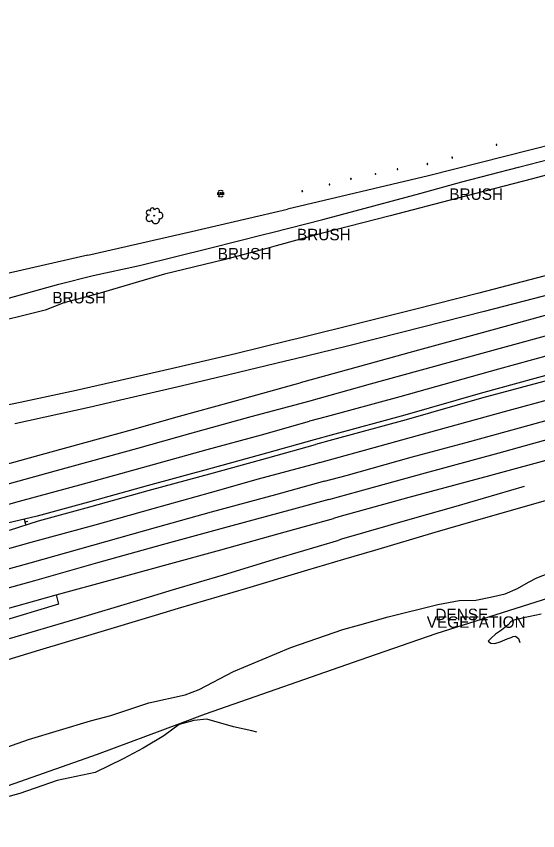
# Model space of a CAD drawing. Extents: x 2129547 to 2134906, y 657330 to 659734.
# Drawn here: x 2134074.5 to 2134392.5, y 658778.9 to 659275.8 of the extents above; entities that cross this region are included whole.
import ezdxf

# ---------------------------------------------------------------- set-up
doc = ezdxf.new("R2010")
doc.units = 0
for name, color, linetype in [('PM_X_Edge_Line', 7, 'Continuous'), ('PM_X_Lane_Line', 7, 'Continuous'), ('PV_X_EOP2', 7, 'Continuous'), ('RD_X_Concrete_Barrier', 7, 'Continuous'), ('RD_X_Fence', 7, 'Continuous'), ('SN_X_Public', 7, 'Continuous'), ('UT_X_Unknown_Cells', 7, 'Continuous'), ('VG_X_Cells', 7, 'Continuous'), ('VG_X_Shrub_Line_Lt', 7, 'Continuous'), ('VG_X_Text', 7, 'Continuous'), ('VG_X_Tree_Line_Lt', 7, 'Continuous')]:
    doc.layers.add(name, color=color, linetype=linetype)

# ---------------------------------------------------------------- blocks, each defined once
blk = doc.blocks.new('SGN1P')
at = {"layer": 'SN_X_Public'}
for p, q in [((0, 0), (-0.02032, 0)), ((0, 0.02032), (0, -0.02032))]:
    blk.add_line(p, q, dxfattribs=at)
blk = doc.blocks.new('TREE')
at = {"layer": 'VG_X_Cells'}
blk.add_circle((0, 0), 0.00305, dxfattribs=at)
for centre, radius, start, end in [((-0.0362, -0.0197), 0.0251, 96.17219, 320.57371), ((-0.042, 0.0237), 0.0187, 39.06254, 279.54124), ((-0.0125, 0.0428), 0.0167, 354.0047, 205.97412), ((0.0232, 0.0359), 0.0197, 323.82996, 165.0376), ((0.0439, 0.0005), 0.0243, 259.14531, 101.45961), ((0.012, -0.0331), 0.029, 184.94757, 19.45715)]:
    blk.add_arc(centre, radius, start, end, dxfattribs=at)
blk = doc.blocks.new('UMH')
at = {"layer": 'UT_X_Unknown_Cells'}
for p, q in [((-0.017, 0.0104), (-0.017, -0.0059)), ((-0.0042, 0.0104), (-0.0042, -0.0059))]:
    blk.add_line(p, q, dxfattribs=at)
blk.add_lwpolyline([(0.0024, -0.01), (0.0024, 0.0104), (0.0099, -0.01), (0.0174, 0.0104), (0.0174, -0.01)], dxfattribs=at)
for centre, radius, start, end in [((0, 0), 0.0254, 160.01689, 200.03919), ((0, 0), 0.0254, 100.0806, 140.07213), ((0, 0), 0.0254, 40.05767, 80.10608), ((0, 0), 0.0254, 340.01689, 20.03919), ((0, 0), 0.0254, 220.05767, 260.04731), ((-0.0106, -0.0029), 0.00708, 205.19243, 334.80757), ((0, 0), 0.0254, 280.01144, 320.02638)]:
    blk.add_arc(centre, radius, start, end, dxfattribs=at)

msp = doc.modelspace()

# ---------------------------------------------------------------- linework, layer by layer
at = {"layer": 'PM_X_Edge_Line'}
for points in [[(2134723.56, 659210.16), (2134667.28, 659193.75), (2134606.38, 659176.46), (2134554.94, 659161.67), (2134501.09, 659146.16), (2134449.29, 659131.67), (2134400.95, 659118.53), (2134356.58, 659106.88), (2134317.3, 659096.98), (2134285.7, 659088.97), (2134246.38, 659079.32), (2134241.17, 659078.04)], [(2134735.23, 659162.91), (2134721.25, 659158.93), (2134671.25, 659144.73), (2134621.41, 659130.82), (2134574.26, 659117.65), (2134524.14, 659103.87), (2134472.09, 659089.42), (2134420.46, 659074.83), (2134368.59, 659060.49), (2134308.4, 659043.65), (2134263.44, 659031.51), (2134253.36, 659028.71)], [(2134259.57, 659003.55), (2134296.43, 659013.77), (2134319.19, 659019.98), (2134374.37, 659035.23), (2134428.42, 659049.97), (2134493.16, 659067.81), (2134550.8, 659083.53), (2134609.4, 659099.69), (2134669.62, 659116.56), (2134732.99, 659133.95), (2134741.79, 659136.38)], [(2134274.16, 658944.52), (2134293.12, 658950.08), (2134329.98, 658961.06), (2134360.83, 658969.97), (2134414.34, 658985.33), (2134461.66, 658999.2), (2134508.88, 659013.57), (2134562.68, 659029.83), (2134598.06, 659040.48), (2134631.84, 659050.6), (2134687.93, 659067.36), (2134745.97, 659084.59), (2134753.99, 659086.98)], [(2134241.17, 659078.04), (2134208.15, 659069.96), (2134171.66, 659061.3), (2134137.78, 659053.5), (2134110.97, 659047.51), (2134076.98, 659040.11), (2134039.58, 659032.47)], [(2134035.26, 658968.3), (2134076.56, 658979.89), (2134115.5, 658990.47), (2134151.38, 659000.44), (2134190.86, 659011.43), (2134223.97, 659020.54), (2134253.36, 659028.71)], [(2134259.57, 659003.55), (2134257.71, 659003.04), (2134222.01, 658993.31), (2134192.71, 658985.12), (2134157.84, 658975.25), (2134122.39, 658965.4), (2134083.48, 658954.83), (2134042.19, 658943.24)], [(2134054.66, 658878.9), (2134088.9, 658889.31), (2134122.12, 658899.2), (2134159.34, 658910.47), (2134173.36, 658914.65), (2134215.11, 658926.97), (2134252.23, 658938.1), (2134274.16, 658944.52)], [(2134061.11, 658912.35), (2134098.82, 658922.76), (2134100.25, 658917.23), (2134063.61, 658906.19)]]:
    msp.add_lwpolyline(points, dxfattribs=at)
at = {"layer": 'PM_X_Lane_Line'}
for points in [[(2134822.61, 659226.18), (2134715.05, 659195.24), (2134675.81, 659183.86), (2134634.77, 659171.94), (2134598.34, 659161.72), (2134557.15, 659150), (2134518.25, 659138.64), (2134480.37, 659127.86), (2134439.61, 659116.6), (2134401.46, 659106.44), (2134359.78, 659095.67), (2134309.38, 659082.83), (2134275.7, 659074.42), (2134243.98, 659066.66)], [(2134825.5, 659214.49), (2134710.32, 659181.19), (2134669.66, 659169.26), (2134629.87, 659158.12), (2134591.41, 659147.43), (2134550.2, 659135.64), (2134511.72, 659124.67), (2134472.82, 659113.69), (2134433.56, 659103.17), (2134394.83, 659092.62), (2134356.4, 659082.11), (2134319.87, 659072.09), (2134283.72, 659062.12), (2134247.56, 659052.18)], [(2134828.43, 659202.6), (2134718.15, 659170.59), (2134676.73, 659158.78), (2134639.29, 659148.33), (2134599.33, 659137.45), (2134563.14, 659127.36), (2134524.01, 659116.49), (2134484.69, 659105.4), (2134445.95, 659094.5), (2134405.86, 659083.18), (2134368.79, 659072.88), (2134329.51, 659062.05), (2134290.35, 659051.26), (2134252.68, 659040.78), (2134250.52, 659040.2)], [(2134262.4, 658992.11), (2134275.67, 658995.74), (2134315.3, 659006.74), (2134348.87, 659015.75), (2134387.16, 659026.4), (2134424.62, 659036.65), (2134465.1, 659047.8), (2134501.55, 659058.17), (2134541.08, 659069), (2134578.8, 659079.33), (2134619.16, 659090.65), (2134657.36, 659101.1), (2134696.06, 659111.65), (2134733.24, 659121.93), (2134841.12, 659151.25)], [(2134265.12, 658981.08), (2134282.76, 658985.93), (2134321.9, 658996.69), (2134368.99, 659009.55), (2134408.45, 659020.37), (2134447.57, 659031.13), (2134487.07, 659041.95), (2134527.16, 659053), (2134564.44, 659063.14), (2134603.55, 659074.07), (2134643.47, 659085.14), (2134685.5, 659096.55), (2134722.02, 659106.56), (2134843.73, 659140.7)], [(2134846.83, 659128.14), (2134716.56, 659092.63), (2134677.17, 659081.8), (2134639.44, 659071.51), (2134598.52, 659060.07), (2134559.43, 659049.32), (2134522.49, 659039.2), (2134482.86, 659028.13), (2134442.03, 659016.71), (2134404.17, 659006.55), (2134363.13, 658995.42), (2134313.89, 658982.15), (2134271.17, 658970.33), (2134268, 658969.46)], [(2134243.98, 659066.66), (2134238.62, 659065.35), (2134204.15, 659056.96), (2134172.34, 659049.53), (2134140.69, 659042.15), (2134118.93, 659037.07), (2134073.54, 659027.1)], [(2134057.34, 658999.52), (2134095.74, 659010.12), (2134145.42, 659023.69), (2134174.01, 659031.74), (2134205.2, 659040.41), (2134244.47, 659051.33), (2134247.56, 659052.18)], [(2134250.52, 659040.2), (2134217.52, 659031.45), (2134180.18, 659021.16), (2134148.4, 659012.06), (2134098.91, 658998.55), (2134060.5, 658987.95)], [(2134262.4, 658992.11), (2134232.55, 658983.94), (2134193.41, 658973.2), (2134160.7, 658964.08), (2134121.02, 658952.97), (2134082.7, 658942.15), (2134045.11, 658931.76)], [(2134384.25, 658989.02), (2134342.57, 658976.8), (2134315.85, 658969.11), (2134272.89, 658956.72), (2134271.26, 658956.23)], [(2134265.12, 658981.08), (2134243.5, 658975.13), (2134203.79, 658964.23), (2134163.45, 658953.33), (2134124.02, 658942.28), (2134085.69, 658931.46), (2134048.03, 658921.05)], [(2134098.82, 658922.76), (2134133.2, 658932.16), (2134166.53, 658941.32), (2134199.16, 658950.33), (2134234.78, 658960.29), (2134268, 658969.46)], [(2134070.45, 658896.19), (2134110.34, 658908.07), (2134148.42, 658919.48), (2134170.41, 658926.19), (2134200.8, 658935.05), (2134234.09, 658945.17), (2134271.26, 658956.23)]]:
    msp.add_lwpolyline(points, dxfattribs=at)
at = {"layer": 'PV_X_EOP2'}
for points in [[(2134241.17, 659078.04), (2134208.15, 659069.96), (2134171.66, 659061.3), (2134137.78, 659053.5), (2134110.97, 659047.51), (2134076.98, 659040.11), (2134039.58, 659032.47)], [(2134035.26, 658968.3), (2134076.56, 658979.89), (2134115.5, 658990.47), (2134151.38, 659000.44), (2134190.86, 659011.43), (2134223.97, 659020.54), (2134253.36, 659028.71)], [(2134259.57, 659003.55), (2134257.71, 659003.04), (2134222.01, 658993.31), (2134192.71, 658985.12), (2134157.84, 658975.25), (2134122.39, 658965.4), (2134083.48, 658954.83), (2134042.19, 658943.24)], [(2134061.11, 658912.35), (2134098.82, 658922.76), (2134100.25, 658917.23), (2134063.61, 658906.19)]]:
    msp.add_lwpolyline(points, dxfattribs=at)
at = {"layer": 'RD_X_Concrete_Barrier'}
for points in [[(2134834.78, 659176.9), (2134697, 659139.23), (2134635.06, 659122.19), (2134589.66, 659109.73), (2134550.72, 659098.97), (2134505.43, 659086.73), (2134472.19, 659077.25), (2134447.11, 659071.29), (2134438.78, 659069.08), (2134435.09, 659068.21), (2134413.68, 659061.14), (2134357.43, 659045.64), (2134311.42, 659032.39), (2134266.53, 659020.26), (2134256.16, 659017.38)], [(2134835.5, 659173.98), (2134697.79, 659136.33), (2134635.86, 659119.29), (2134590.45, 659106.84), (2134551.51, 659096.07), (2134506.21, 659083.83), (2134472.85, 659074.37), (2134449.45, 659067.1), (2134436.3, 659063.72), (2134405.29, 659055.38), (2134358.24, 659042.75), (2134312.22, 659029.5), (2134267.32, 659017.37), (2134256.88, 659014.47)], [(2134256.16, 659017.38), (2134227.07, 659009.3), (2134193.97, 659000.19), (2134154.24, 658989.3), (2134118.55, 658979.38), (2134087.23, 658970.87), (2134069.21, 658966.66)], [(2134070.34, 658962.31), (2134087.99, 658967.97), (2134119.34, 658976.49), (2134154.98, 658986.39), (2134194.77, 658997.3), (2134227.87, 659006.41), (2134256.88, 659014.47)]]:
    msp.add_lwpolyline(points, dxfattribs=at)
at = {"layer": 'RD_X_Fence'}
for p, q in [((2134222.39, 659154.05), (2134239.8, 659158.08)), ((2134288.93, 658884.72), (2134330.51, 658899.2)), ((2134189.88, 658850.21), (2134288.93, 658884.72))]:
    msp.add_line(p, q, dxfattribs=at)
for points in [[(2134707.34, 659275.8), (2134661.3, 659263.97), (2134583.68, 659244.07), (2134510.36, 659225.5), (2134418.95, 659202.15), (2134325.8, 659178.53), (2134239.8, 659158.08)], [(2134118.14, 659130.16), (2134181.41, 659144.55), (2134222.39, 659154.05)], [(2134118.14, 659130.16), (2134070.98, 659119.25), (2134019.86, 659107.98), (2133977.41, 659097.6), (2133937.58, 659086.88), (2133891.52, 659073.98), (2133829.38, 659057.65), (2133758.68, 659038.54), (2133682.08, 659017.72), (2133636.81, 659005.08), (2133582.59, 658990.71), (2133537.62, 658978.61), (2133480.02, 658962.66), (2133435.74, 658950.56), (2133375.25, 658933.98), (2133331.89, 658921.65)], [(2134330.51, 658899.2), (2134411.41, 658924.97), (2134550.15, 658969.27), (2134626.91, 658991.22), (2134714.37, 659015.06), (2134768.19, 659029.53)], [(2133974.46, 658778.93), (2133974.8, 658779.03), (2134016.03, 658788.92), (2134058.67, 658802.57), (2134123.95, 658825.55), (2134174.2, 658844.34), (2134189.88, 658850.21)]]:
    msp.add_lwpolyline(points, dxfattribs=at)
at = {"layer": 'VG_X_Cells'}
for centre in [(2134367.3, 659197.36), (2134340.28, 659189.54), (2134325.18, 659185.66), (2134293.52, 659179.54), (2134306.9, 659182.51), (2134278.63, 659176.64), (2134248.92, 659169.08), (2134265.52, 659173.21)]:
    msp.add_circle(centre, 0.012, dxfattribs=at)
for centre, radius, start, end in [((2134367.13, 659197.45), 0.0735, 39.0625, 279.5412), ((2134367.15, 659197.28), 0.0987, 96.1722, 320.5737), ((2134367.25, 659197.53), 0.0658, 354.0047, 205.9741), ((2134367.34, 659197.23), 0.114, 184.9476, 19.4572), ((2134367.39, 659197.5), 0.0776, 323.83, 165.0376), ((2134367.47, 659197.36), 0.0957, 259.1453, 101.4596), ((2134340.12, 659189.63), 0.0735, 39.0625, 279.5412), ((2134340.14, 659189.46), 0.0987, 96.1722, 320.5737), ((2134340.23, 659189.71), 0.0658, 354.0047, 205.9741), ((2134340.33, 659189.41), 0.114, 184.9476, 19.4572), ((2134340.37, 659189.68), 0.0776, 323.83, 165.0376), ((2134340.45, 659189.54), 0.0957, 259.1453, 101.4596), ((2134325.02, 659185.75), 0.0735, 39.0625, 279.5412), ((2134325.04, 659185.58), 0.0987, 96.1722, 320.5737), ((2134325.13, 659185.83), 0.0658, 354.0047, 205.9741), ((2134325.23, 659185.53), 0.114, 184.9476, 19.4572), ((2134325.27, 659185.8), 0.0776, 323.83, 165.0376), ((2134325.36, 659185.66), 0.0957, 259.1453, 101.4596), ((2134293.38, 659179.47), 0.0987, 96.1722, 320.5737), ((2134293.36, 659179.64), 0.0735, 39.0625, 279.5412), ((2134293.48, 659179.71), 0.0658, 354.0047, 205.9741), ((2134293.57, 659179.41), 0.114, 184.9476, 19.4572), ((2134293.62, 659179.69), 0.0776, 323.83, 165.0376), ((2134293.7, 659179.55), 0.0957, 259.1453, 101.4596), ((2134306.76, 659182.43), 0.0987, 96.1722, 320.5737), ((2134306.74, 659182.6), 0.0735, 39.0625, 279.5412), ((2134306.86, 659182.68), 0.0658, 354.0047, 205.9741), ((2134306.95, 659182.38), 0.114, 184.9476, 19.4572), ((2134307, 659182.65), 0.0776, 323.83, 165.0376), ((2134307.08, 659182.51), 0.0957, 259.1453, 101.4596), ((2134278.47, 659176.73), 0.0735, 39.0625, 279.5412), ((2134278.49, 659176.56), 0.0987, 96.1722, 320.5737), ((2134278.58, 659176.81), 0.0658, 354.0047, 205.9741), ((2134278.68, 659176.51), 0.114, 184.9476, 19.4572), ((2134278.72, 659176.78), 0.0776, 323.83, 165.0376), ((2134278.81, 659176.64), 0.0957, 259.1453, 101.4596), ((2134248.75, 659169.17), 0.0735, 39.0625, 279.5412), ((2134248.77, 659169), 0.0987, 96.1722, 320.5737), ((2134248.87, 659169.25), 0.0658, 354.0047, 205.9741), ((2134248.96, 659168.95), 0.114, 184.9476, 19.4572), ((2134249.01, 659169.22), 0.0776, 323.83, 165.0376), ((2134249.09, 659169.08), 0.0957, 259.1453, 101.4596), ((2134265.37, 659173.13), 0.0987, 96.1722, 320.5737), ((2134265.35, 659173.3), 0.0735, 39.0625, 279.5412), ((2134265.47, 659173.38), 0.0658, 354.0047, 205.9741), ((2134265.56, 659173.08), 0.114, 184.9476, 19.4572), ((2134265.61, 659173.35), 0.0776, 323.83, 165.0376), ((2134265.69, 659173.21), 0.0957, 259.1453, 101.4596)]:
    msp.add_arc(centre, radius, start, end, dxfattribs=at)
at = {"layer": 'VG_X_Shrub_Line_Lt'}
for p, q in [((2134225.22, 659142.58), (2134230.36, 659143.88)), ((2134232.89, 659135.68), (2134227.29, 659134.2))]:
    msp.add_line(p, q, dxfattribs=at)
for points in [[(2134711.3, 659259.78), (2134711.08, 659259.71), (2134676.33, 659250.7), (2134635.58, 659240.44), (2134598.06, 659230.48), (2134558.43, 659220.49), (2134517.52, 659210.54), (2134473.14, 659199.12), (2134428.66, 659187.23), (2134389.19, 659176.66), (2134342.91, 659164.6), (2134302.43, 659154.14), (2134260.35, 659143.37), (2134232.89, 659135.68)], [(2134230.36, 659143.88), (2134261.36, 659151.91), (2134292.59, 659160.14), (2134320.5, 659167.72), (2134346.29, 659174.88), (2134380.68, 659183.69), (2134418.55, 659193.46)], [(2134066.18, 659102.82), (2134100.45, 659112.32), (2134121.32, 659117.72), (2134149.56, 659123.84), (2134193.13, 659134.5), (2134225.22, 659142.58)], [(2134227.29, 659134.2), (2134201.09, 659127.23), (2134164.91, 659118.4), (2134124.21, 659106.48), (2134103.47, 659100.88), (2134092.14, 659096.55), (2134083.19, 659094.34), (2134063.23, 659089.41)]]:
    msp.add_lwpolyline(points, dxfattribs=at)
at = {"layer": 'VG_X_Tree_Line_Lt'}
msp.add_line((2134284.01, 658904.63), (2134301.2, 658909.47), dxfattribs=at)
for points in [[(2134301.2, 658909.47), (2134331.52, 658916.95), (2134344.53, 658919.28), (2134354.73, 658919.65), (2134363.64, 658921.37), (2134372.52, 658923.47), (2134380.08, 658926.63), (2134386.77, 658930.5), (2134391.94, 658933.13), (2134399.24, 658936.15)], [(2134394.48, 658911.11), (2134386.77, 658909.44), (2134383.8, 658908.73), (2134380.82, 658908), (2134378.77, 658907.65), (2134377.19, 658907.26), (2134376.04, 658906.44), (2134374.38, 658904.57), (2134372.49, 658902.88), (2134370.39, 658901.26), (2134366.68, 658898.81), (2134364.03, 658896.32), (2134362.21, 658894.62), (2134363.93, 658893.26), (2134366.33, 658893.2), (2134369.53, 658894.21), (2134373.86, 658896.05), (2134376.25, 658896.89), (2134377.44, 658897.4), (2134378.87, 658897.53), (2134380.75, 658896.19), (2134381.53, 658893.72)], [(2134039.95, 658819.69), (2134081.89, 658834.58), (2134119.8, 658845.97), (2134132.23, 658849.3), (2134155.42, 658856.87), (2134177.58, 658861.82), (2134186.06, 658865.1), (2134207.01, 658876.14), (2134242.02, 658890.68), (2134273.73, 658901.74), (2134284.01, 658904.63)], [(2134221.13, 658839.12), (2134218.08, 658839.78), (2134206.93, 658842.3), (2134190.7, 658847), (2134182.86, 658846.09), (2134173.77, 658843.74), (2134164.41, 658836.77), (2134151.91, 658829.27), (2134139.75, 658822.78), (2134122.55, 658814.37), (2134099.37, 658809.59), (2134076.6, 658801.57), (2134050.63, 658794.46)]]:
    msp.add_lwpolyline(points, dxfattribs=at)

# ---------------------------------------------------------------- block references
at = {"layer": 'SN_X_Public', "xscale": 78.74000000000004, "yscale": 78.74000000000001, "rotation": -165.4600293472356}
msp.add_blockref('SGN1P', (2134080.01, 658967.3), dxfattribs=at)
at = {"layer": 'UT_X_Unknown_Cells', "xscale": 78.74000000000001, "yscale": 78.74000000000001}
msp.add_blockref('UMH', (2134199.15, 659167.64), dxfattribs=at)
at = {"layer": 'VG_X_Cells', "xscale": 78.74000000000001, "yscale": 78.74000000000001}
msp.add_blockref('TREE', (2134158.52, 659154.19), dxfattribs=at)

# ---------------------------------------------------------------- texts
at = {"layer": 'VG_X_Text'}
for s, p in [('BRUSH', (2134338.56, 659163.79)), ('BRUSH', (2134245.66, 659139.13)), ('BRUSH', (2134197.33, 659127.44)), ('BRUSH', (2134096.46, 659100.64)), ('DENSE', (2134330.05, 658907.37)), ('VEGETATION', (2134324.79, 658902.71))]:
    msp.add_text(s, height=7, dxfattribs=at).set_placement(p)

doc.saveas('drawing.dxf')
